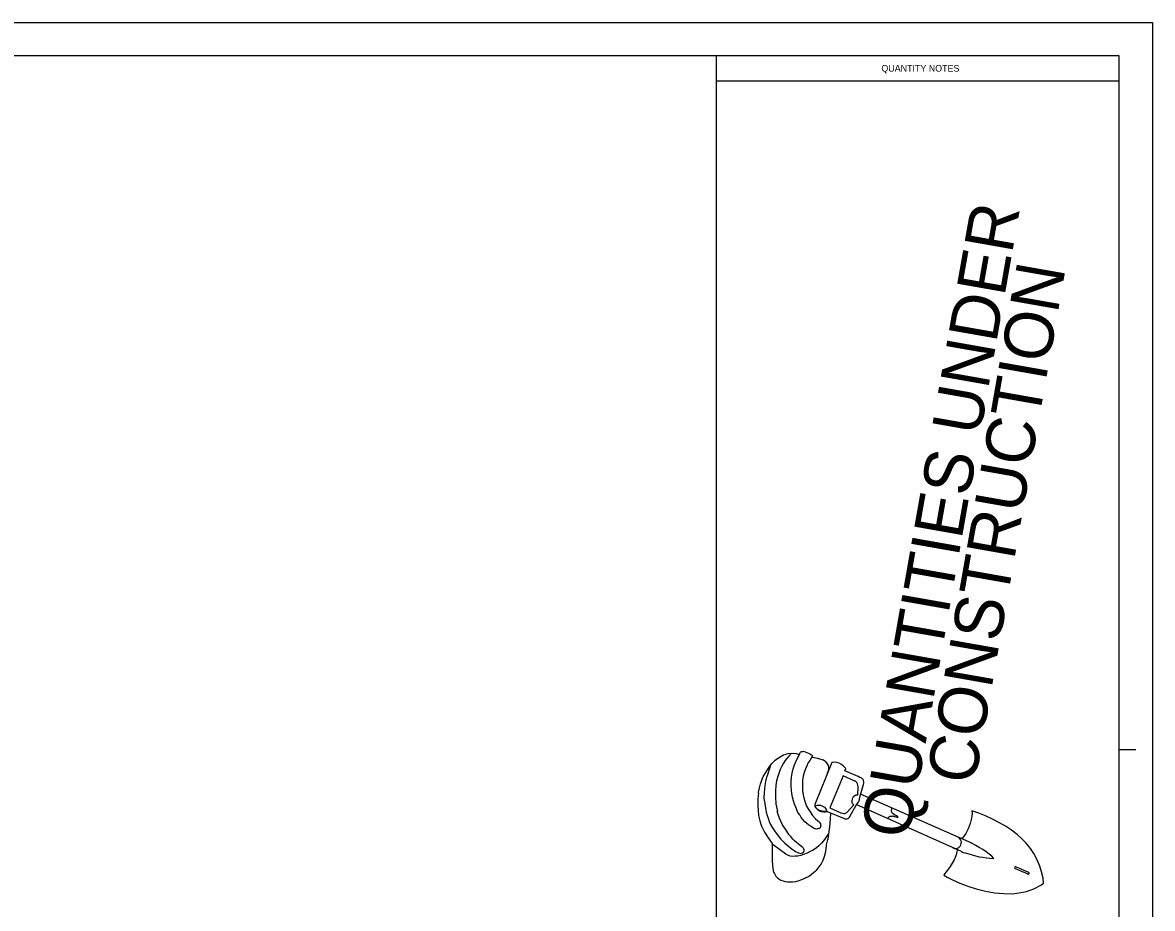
# Model space of a CAD drawing. Extents: x 0 to 34, y 0 to 22.
# Drawn here: x 17 to 34, y 8.67 to 22 of the extents above; entities that cross this region are included whole.
import ezdxf

# ---------------------------------------------------------------- set-up
doc = ezdxf.new("R2010")
doc.units = 0
for name, color, linetype in [('BORD-LINE', 7, 'Continuous'), ('QNTY-LINE', 7, 'Continuous'), ('QNTY-NOTE', 7, 'Continuous'), ('USER-PAGE', 7, 'Continuous')]:
    doc.layers.add(name, color=color, linetype=linetype)

msp = doc.modelspace()

# ---------------------------------------------------------------- linework, layer by layer
at = {"layer": 'BORD-LINE'}
msp.add_line((33.5, 11.062), (33.75, 11.062), dxfattribs=at)
msp.add_lwpolyline([(1.5, 0.75), (33.5, 0.75), (33.5, 21.5), (1.5, 21.5)], close=True, dxfattribs=at)
at = {"layer": 'QNTY-LINE'}
for p, q in [((27.437, 21.5), (27.437, 5)), ((27.437, 21.125), (33.5, 21.125))]:
    msp.add_line(p, q, dxfattribs=at)
at = {"layer": 'QNTY-NOTE'}
for p, q in [((31.281, 9.651), (29.607, 10.387)), ((31.13, 9.524), (29.544, 10.233)), ((31.13, 9.524), (31.154, 9.513)), ((31.13, 9.524), (31.154, 9.513)), ((31.154, 9.513), (31.183, 9.508)), ((31.936, 9.269), (32.125, 9.188)), ((31.948, 9.297), (32.137, 9.215))]:
    msp.add_line(p, q, dxfattribs=at)
for points in [[(28.072, 10.403), (28.075, 10.418), (28.09, 10.484), (28.104, 10.542), (28.124, 10.598), (28.144, 10.653), (28.181, 10.717), (28.221, 10.78), (28.268, 10.843), (28.326, 10.903), (28.388, 10.947), (28.451, 10.979), (28.519, 10.999), (28.59, 11.004), (28.64, 11.002), (28.691, 10.988), (28.697, 11.002), (28.705, 11.019), (28.71, 11.024), (28.717, 11.028), (28.721, 11.031), (28.73, 11.031), (28.735, 11.032), (28.743, 11.033), (28.751, 11.034), (28.823, 11.006), (28.844, 10.998), (28.858, 10.987), (28.872, 10.98), (28.878, 10.974), (28.882, 10.97), (28.883, 10.961), (28.886, 10.948), (28.886, 10.948)], [(28.57, 11.004), (28.527, 10.963), (28.502, 10.929), (28.474, 10.897), (28.449, 10.857), (28.425, 10.811), (28.401, 10.762), (28.362, 10.654), (28.346, 10.589), (28.334, 10.517), (28.329, 10.441), (28.327, 10.345), (28.334, 10.242), (28.358, 10.128)], [(28.885, 10.964), (28.843, 10.898), (28.816, 10.853), (28.799, 10.813), (28.779, 10.77), (28.761, 10.717), (28.745, 10.66), (28.737, 10.595), (28.733, 10.512), (28.734, 10.444), (28.747, 10.379), (28.762, 10.312), (28.774, 10.267), (28.797, 10.209), (28.821, 10.166), (28.848, 10.123), (28.886, 10.07), (28.925, 10.024), (28.968, 9.987), (28.99, 9.968), (28.997, 9.959), (29.005, 9.941), (29.007, 9.929), (29.01, 9.917), (29.008, 9.901), (29.004, 9.894), (29.002, 9.888), (28.999, 9.88), (28.993, 9.875), (28.986, 9.87), (28.978, 9.87), (28.972, 9.864), (28.963, 9.865), (28.954, 9.865), (28.947, 9.864), (28.933, 9.869), (28.922, 9.869), (28.902, 9.878), (28.88, 9.892), (28.857, 9.906), (28.826, 9.928), (28.799, 9.948), (28.77, 9.972), (28.742, 10.008), (28.715, 10.04), (28.693, 10.078), (28.667, 10.112), (28.649, 10.153), (28.634, 10.192), (28.614, 10.241), (28.601, 10.291), (28.584, 10.346), (28.574, 10.397), (28.569, 10.451), (28.566, 10.508), (28.566, 10.589), (28.568, 10.633)], [(28.569, 10.628), (28.571, 10.647), (28.58, 10.707), (28.595, 10.77), (28.614, 10.83), (28.634, 10.877), (28.669, 10.949), (28.691, 10.988)], [(28.886, 10.948), (28.962, 10.93), (29.04, 10.905)], [(28.163, 10.288), (28.16, 10.337), (28.163, 10.408), (28.166, 10.471), (28.172, 10.521), (28.184, 10.579), (28.197, 10.646), (28.211, 10.684), (28.257, 10.828)], [(29.602, 10.364), (29.654, 10.534), (29.66, 10.554), (29.66, 10.574), (29.654, 10.597), (29.646, 10.613), (29.63, 10.624), (29.619, 10.633), (29.598, 10.641), (29.572, 10.653), (29.372, 10.74), (29.385, 10.774), (29.371, 10.792), (29.348, 10.815), (29.321, 10.833), (29.285, 10.854), (29.253, 10.864), (29.22, 10.871), (29.188, 10.868), (29.175, 10.866), (28.92, 10.235), (28.921, 10.218), (28.927, 10.196), (28.94, 10.178), (28.962, 10.157), (28.991, 10.14), (29.018, 10.128), (29.051, 10.123), (29.079, 10.122), (29.105, 10.127), (29.354, 10.027), (29.371, 10.019), (29.391, 10.018), (29.407, 10.02), (29.422, 10.025), (29.433, 10.032), (29.442, 10.044), (29.452, 10.057), (29.454, 10.063), (29.538, 10.211)], [(29.568, 10.379), (29.573, 10.493), (29.57, 10.522), (29.563, 10.544), (29.553, 10.565), (29.544, 10.573), (29.532, 10.583), (29.522, 10.587), (29.347, 10.663), (29.146, 10.182), (29.31, 10.109), (29.339, 10.101), (29.357, 10.097), (29.374, 10.098), (29.388, 10.105), (29.399, 10.112), (29.407, 10.119), (29.506, 10.229), (29.498, 10.237), (29.489, 10.245), (29.481, 10.263), (29.48, 10.288), (29.487, 10.313), (29.492, 10.335), (29.504, 10.354), (29.521, 10.371), (29.539, 10.378), (29.552, 10.381), (29.568, 10.379)], [(28.072, 10.403), (28.067, 10.362), (28.065, 10.322), (28.062, 10.267), (28.063, 10.215), (28.066, 10.15), (28.073, 10.066), (28.093, 9.99), (28.12, 9.906), (28.165, 9.815), (28.218, 9.732), (28.278, 9.649), (28.284, 9.638)], [(28.163, 10.288), (28.167, 10.243), (28.172, 10.208), (28.181, 10.156), (28.188, 10.116), (28.205, 10.07), (28.217, 10.028), (28.236, 9.98), (28.255, 9.931), (28.282, 9.884), (28.312, 9.839), (28.355, 9.78), (28.405, 9.715), (28.47, 9.65), (28.528, 9.601), (28.576, 9.564), (28.632, 9.528), (28.675, 9.505), (28.709, 9.498), (28.721, 9.5), (28.737, 9.506), (28.748, 9.514), (28.757, 9.526), (28.762, 9.54), (28.76, 9.552), (28.754, 9.567), (28.746, 9.578), (28.742, 9.584), (28.726, 9.595), (28.697, 9.62), (28.67, 9.643), (28.643, 9.663), (28.617, 9.685), (28.59, 9.714), (28.558, 9.753), (28.528, 9.784), (28.497, 9.83), (28.468, 9.875), (28.435, 9.929), (28.41, 9.981), (28.391, 10.029), (28.369, 10.083), (28.355, 10.132)], [(28.929, 10.207), (28.938, 10.219), (28.956, 10.224), (28.983, 10.224), (29.006, 10.221), (29.026, 10.213), (29.044, 10.205), (29.065, 10.192), (29.082, 10.174), (29.093, 10.16), (29.097, 10.155), (29.097, 10.147), (29.095, 10.139), (29.089, 10.134), (29.084, 10.133), (29.078, 10.126), (29.065, 10.128), (29.046, 10.128), (29.031, 10.132), (29.009, 10.137), (28.991, 10.14), (28.973, 10.153), (28.957, 10.163), (28.946, 10.172), (28.931, 10.186), (28.927, 10.196), (28.927, 10.204), (28.929, 10.207)], [(29.598, 10.366), (29.59, 10.312), (29.588, 10.298), (29.583, 10.287), (29.577, 10.274), (29.569, 10.262), (29.532, 10.214)], [(29.155, 10.105), (29.151, 10.011), (29.143, 9.899), (29.123, 9.75), (29.115, 9.706)], [(30.012, 10.021), (30.046, 10.051), (30.053, 10.056), (30.065, 10.059), (30.077, 10.058), (30.086, 10.058), (30.099, 10.061), (30.111, 10.055), (30.126, 10.052), (30.14, 10.046), (30.153, 10.041), (30.165, 10.04), (30.171, 10.045), (30.173, 10.049), (30.167, 10.054), (30.147, 10.062), (30.127, 10.072), (30.118, 10.08), (30.1, 10.091), (30.088, 10.102), (30.08, 10.112), (30.079, 10.12), (30.074, 10.126), (30.072, 10.131), (30.081, 10.177)], [(31.06, 9.545), (31.055, 9.524), (31.051, 9.497), (31.043, 9.461), (31.017, 9.401), (30.987, 9.35), (30.957, 9.298), (30.917, 9.244), (30.879, 9.196), (30.861, 9.168), (30.913, 9.142), (30.994, 9.099), (31.102, 9.051), (31.224, 9.003), (31.348, 8.964), (31.488, 8.927), (31.622, 8.905), (31.765, 8.892), (31.896, 8.89), (31.995, 8.904), (32.108, 8.926), (32.214, 8.964), (32.329, 9.027), (32.359, 9.05), (32.355, 9.123), (32.333, 9.222), (32.308, 9.308), (32.26, 9.413), (32.216, 9.496), (32.168, 9.57), (32.101, 9.654), (32.032, 9.721), (31.964, 9.782), (31.882, 9.845), (31.792, 9.905), (31.7, 9.958), (31.595, 10.014), (31.488, 10.061), (31.388, 10.105), (31.285, 10.138), (31.287, 10.096), (31.278, 10.029), (31.258, 9.948), (31.229, 9.869), (31.193, 9.797), (31.154, 9.741), (31.136, 9.722), (31.122, 9.726)], [(28.279, 9.645), (28.278, 9.382), (28.282, 9.328), (28.288, 9.268), (28.3, 9.215), (28.312, 9.195), (28.323, 9.173), (28.335, 9.155), (28.357, 9.13), (28.377, 9.113), (28.409, 9.096), (28.444, 9.084), (28.476, 9.074), (28.511, 9.072), (28.546, 9.069), (28.591, 9.072), (28.634, 9.077), (28.683, 9.088), (28.711, 9.1), (28.751, 9.116), (28.791, 9.134), (28.826, 9.15), (28.867, 9.181), (28.903, 9.209), (28.949, 9.25), (28.985, 9.295), (29.014, 9.338), (29.04, 9.386), (29.064, 9.449), (29.08, 9.505), (29.093, 9.563), (29.096, 9.627), (29.115, 9.706)], [(29.127, 9.798), (29.078, 9.722), (29.05, 9.687), (29.019, 9.652), (28.982, 9.612), (28.944, 9.58), (28.894, 9.546), (28.852, 9.524), (28.806, 9.5), (28.752, 9.479), (28.708, 9.467), (28.666, 9.456), (28.625, 9.454), (28.593, 9.452), (28.551, 9.458), (28.516, 9.471), (28.484, 9.488), (28.295, 9.626)], [(31.613, 9.421), (31.582, 9.455), (31.544, 9.487), (31.5, 9.519), (31.448, 9.554), (31.391, 9.587), (31.343, 9.616), (31.298, 9.642), (31.236, 9.674)], [(31.183, 9.508), (31.236, 9.49), (31.29, 9.475), (31.337, 9.462), (31.394, 9.448), (31.45, 9.44), (31.502, 9.43), (31.557, 9.426), (31.613, 9.421)]]:
    msp.add_lwpolyline(points, dxfattribs=at)
for centre, radius, start, end in [((28.996, 10.776), 0.135, 325.9935, 71.5172), ((31.037, 9.661), 0.0886, 244.7925, 66.6847), ((31.037, 9.661), 0.0886, 244.7925, 66.6847), ((31.942, 9.283), 0.0151, 66.7295, 246.7298), ((32.131, 9.201), 0.0148, 246.7298, 66.7296)]:
    msp.add_arc(centre, radius, start, end, dxfattribs=at)
at = {"layer": 'USER-PAGE'}
msp.add_lwpolyline([(0, 22), (34, 22), (34, 0), (0, 0)], close=True, dxfattribs=at)

# ---------------------------------------------------------------- texts
at = {"layer": 'QNTY-LINE'}
msp.add_text('QUANTITY NOTES', height=0.1, dxfattribs=at).set_placement((29.922, 21.262))
at = {"layer": 'QNTY-NOTE'}
for s, p in [('QUANTITIES UNDER', (30.332, 9.693)), ('CONSTRUCTION', (31.322, 10.512))]:
    msp.add_text(s, height=0.73471, rotation=80, dxfattribs=at).set_placement(p)

doc.saveas('drawing.dxf')
